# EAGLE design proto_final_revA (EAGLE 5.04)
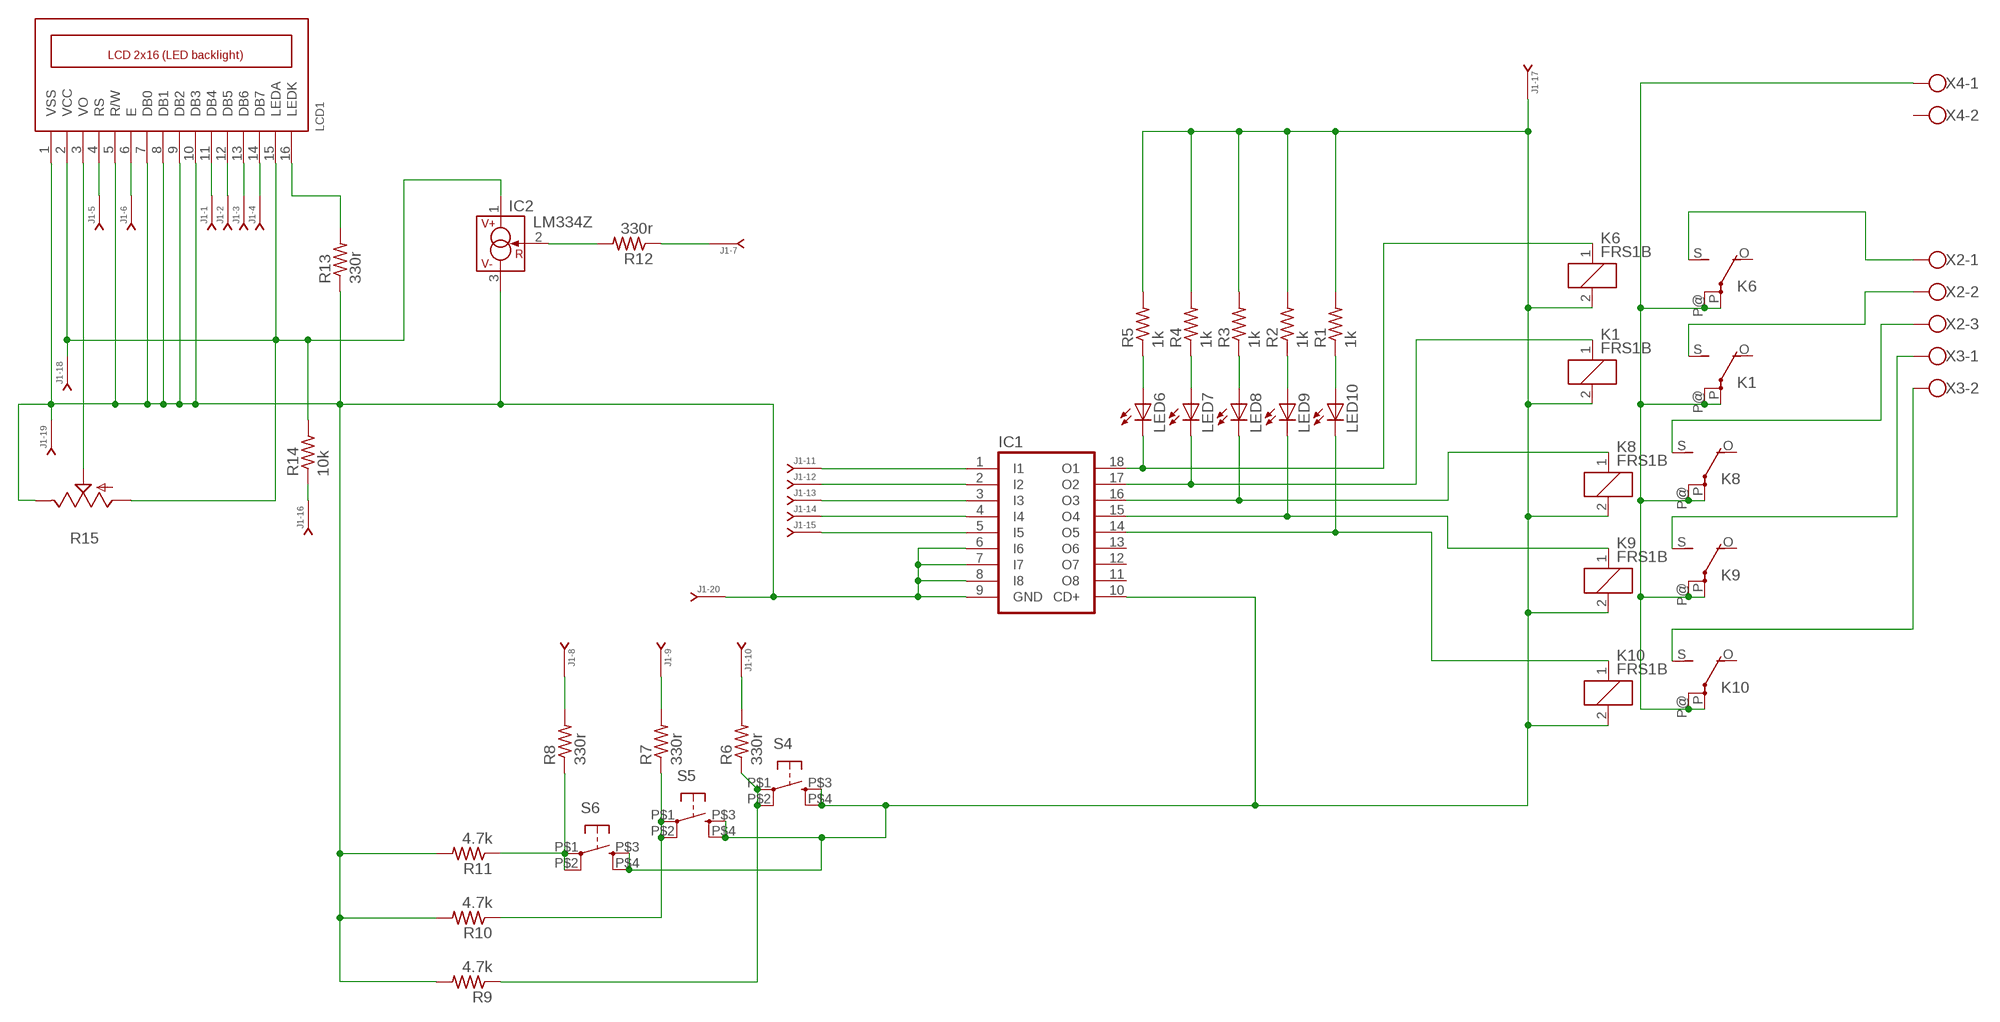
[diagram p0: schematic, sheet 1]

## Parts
IC1  ULN2803A  [DIL18]
IC2  LM334Z  [TO92]
J1  J-20-100-2X10  [HDR-100-2X10]
K1  FRS1B  [FRS1B]
K6  FRS1B  [FRS1B]
K8  FRS1B  [FRS1B]
K9  FRS1B  [FRS1B]
K10  FRS1B  [FRS1B]
LCD1  LCD_2X16_SIL  [HY-1602F]
LED6  LED5MM  [LED5MM]
LED7  LED5MM  [LED5MM]
LED8  LED5MM  [LED5MM]
LED9  LED5MM  [LED5MM]
LED10  LED5MM  [LED5MM]
R1  1k  R-US_0207/10  [0207/10]
R2  1k  R-US_0207/10  [0207/10]
R3  1k  R-US_0207/10  [0207/10]
R4  1k  R-US_0207/10  [0207/10]
R5  1k  R-US_0207/10  [0207/10]
R6  330r  R-US_0207/10  [0207/10]
R7  330r  R-US_0207/10  [0207/10]
R8  330r  R-US_0207/10  [0207/10]
R9  4.7k  R-US_0207/10  [0207/10]
R10  4.7k  R-US_0207/10  [0207/10]
R11  4.7k  R-US_0207/10  [0207/10]
R12  330r  R-US_0207/10  [0207/10]
R13  330r  R-US_0207/10  [0207/10]
R14  10k  R-US_0207/10  [0207/10]
R15  TRIM_US-CT6  [CT6]
S4  TAC_SWITCHKSA_SEALED  [KSA_SEALED_TAC_SWITCH]
S5  TAC_SWITCHKSA_SEALED  [KSA_SEALED_TAC_SWITCH]
S6  TAC_SWITCHKSA_SEALED  [KSA_SEALED_TAC_SWITCH]
X2  W237-103  [W237-103]
X3  W237-102  [W237-102]
X4  W237-102  [W237-102]

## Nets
GROUND: IC1.6(I6) IC1.7(I7) IC1.8(I8) IC1.9(GND) IC2.3(V-) J1.19 J1.20 LCD1.1(VSS) LCD1.5(R/W) LCD1.7(DB0) LCD1.8(DB1) LCD1.9(DB2) LCD1.10(DB3) R9.2 R10.2 R11.2 R13.1 R15.E
N$1: J1.6 LCD1.6(E)
N$2: J1.5 LCD1.4(RS)
N$3: J1.1 LCD1.11(DB4)
N$4: J1.2 LCD1.12(DB5)
N$5: J1.3 LCD1.13(DB6)
N$6: J1.4 LCD1.14(DB7)
N$7: IC2.2(R) R12.2
N$8: J1.7 R12.1
N$9: J1.8 R8.2
N$10: J1.9 R7.2
N$11: R8.1 R11.1 S6.P$1 S6.P$2
N$12: IC1.10(CD+) J1.17 K1.2 K6.2 K8.2 K9.2 K10.2 R1.2 R2.2 R3.2 R4.2 R5.2 S4.P$3 S4.P$4 S5.P$3 S5.P$4 S6.P$3 S6.P$4
N$13: LED6.A R5.1
N$14: K6.S(2:S) X2.1
N$15: K1.P(2:P) K1.P@(2:P) K6.P(2:P) K6.P@(2:P) K8.P(2:P) K8.P@(2:P) K9.P(2:P) K9.P@(2:P) K10.P(2:P) K10.P@(2:P) X4.1
N$16: J1.10 R6.2
N$17: IC1.1(I1) J1.11
N$18: IC1.2(I2) J1.12
N$19: IC1.3(I3) J1.13
N$20: IC1.4(I4) J1.14
N$21: IC1.5(I5) J1.15
N$22: LED7.A R4.1
N$23: LED8.A R3.1
N$24: LED9.A R2.1
N$25: LED10.A R1.1
N$26: IC1.18(O1) K6.1 LED6.K(C)
N$27: IC1.17(O2) K1.1 LED7.K(C)
N$28: IC2.1(V+) J1.18 LCD1.2(VCC) LCD1.15(LEDA) R14.2 R15.A
N$29: IC1.15(O4) K9.1 LED9.K(C)
N$30: IC1.14(O5) K10.1 LED10.K(C)
N$31: K1.S(2:S) X2.2
N$32: R7.1 R10.1 S5.P$1 S5.P$2
N$33: K8.S(2:S) X2.3
N$34: R6.1 R9.1 S4.P$1 S4.P$2
N$35: LCD1.3(VO) R15.S
N$36: IC1.16(O3) K8.1 LED8.K(C)
N$37: K9.S(2:S) X3.1
N$38: K10.S(2:S) X3.2
N$39: LCD1.16(LEDK) R13.2
N$40: J1.16 R14.1
Unconnected: IC1.11(O8) IC1.12(O7) IC1.13(O6) K1.O(2:O) K6.O(2:O) K8.O(2:O) K9.O(2:O) K10.O(2:O) X4.2

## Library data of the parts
IC1 = uln-udn:ULN2803A: DRIVER ARRAY
IC2 = linear:LM*34: 3-Terminal Adjustable Current Sources Source: www.national.com/pf/LM/LM334.html | LM134.pdf
J1 = con-headers-jp:J-20-: HEADER JACK PINS
K1 K6 K8-K10 = mgd:FRS1B: RELAY 1 x switch, same as V23101-D6-A201, Siemens
LCD1 = lcd_2x16_led_backlight:LCD_2X16_SIL
LED6-LED10 = SparkFun:LED: LEDs
R1-R14 = resistor:R-US_: RESISTOR, American symbol
R15 = pot:TRIM_US-: POTENTIOMETER
S4-S6 = SparkFun:TAC_SWITCH: Momentary Switch Button commonly used for reset or general input. Spark Fun Electronics SKU : COM-00097
X2 = con-wago-500:W237-103: WAGO SCREW CLAMP
X3 X4 = con-wago-500:W237-102: WAGO SCREW CLAMP

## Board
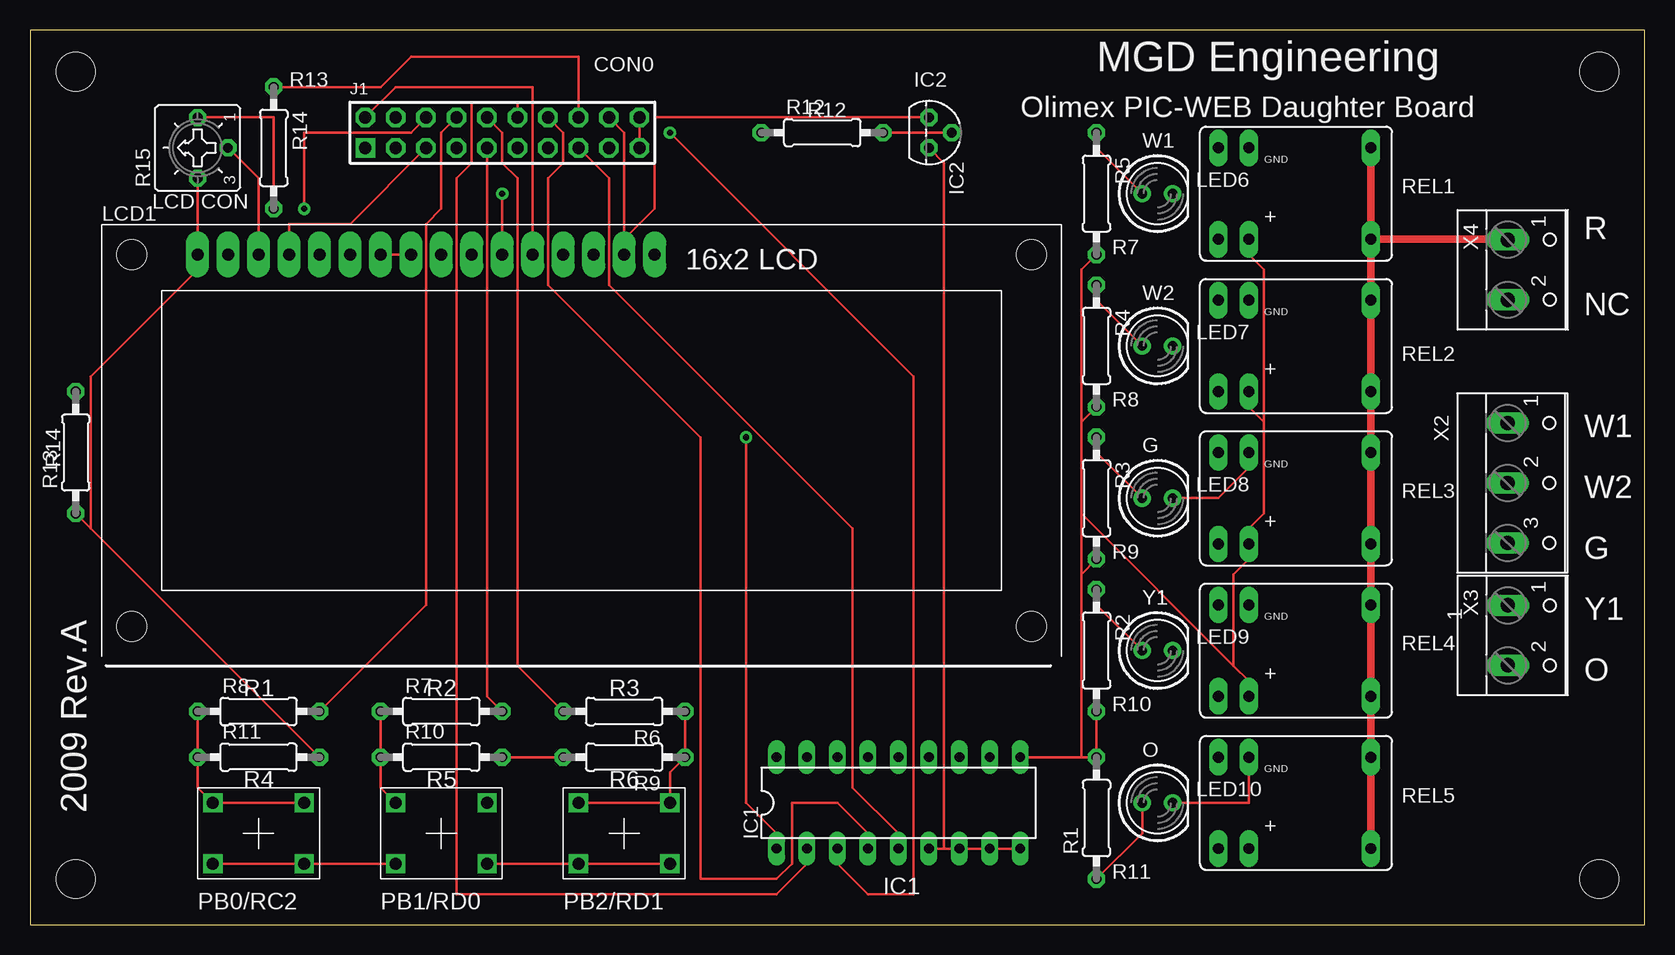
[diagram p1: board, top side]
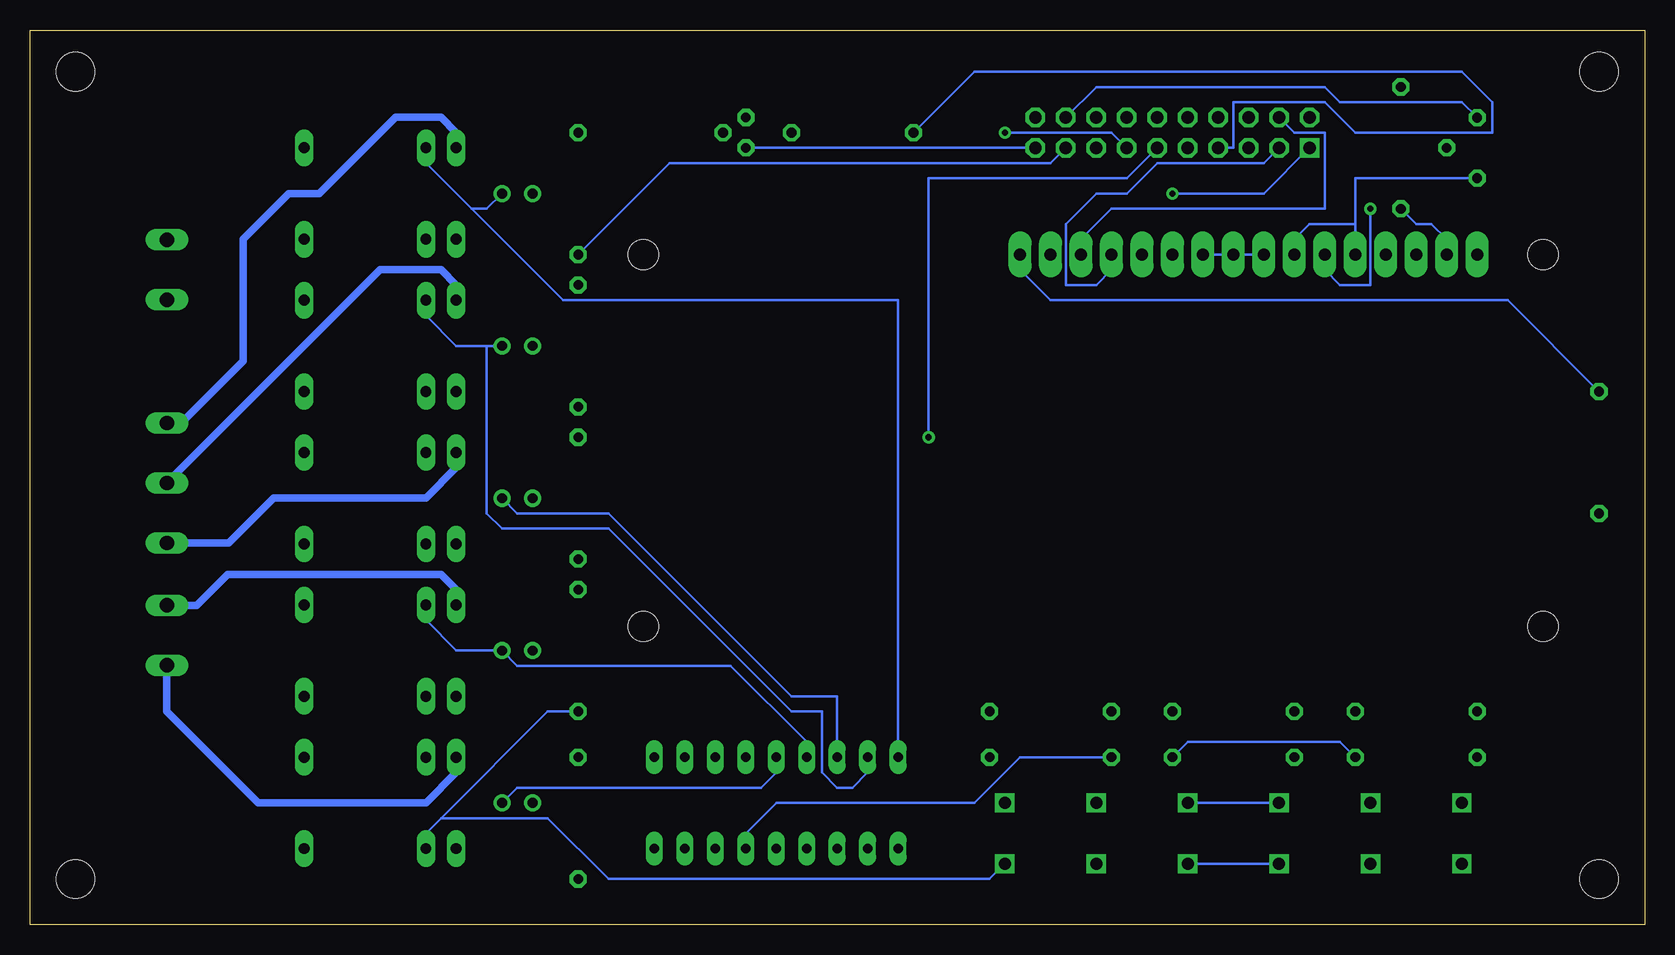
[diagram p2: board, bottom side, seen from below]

Size 134.6 x 74.6 mm. Coordinates in mm from the lower left corner, seen from the top.
Outline: 0,0 134.6,0 134.6,74.6 0,74.6 0,0
Copper layers (1*16): Top 0.035mm / dielectric 1.5mm / Bottom 0.035mm
Design rules "SparkFun": minimum track width 8mil, minimum drill 20mil, track to track 8mil, track to pad 8mil, pad to pad 8mil, via to via 8mil, smd to smd 8mil, copper to edge 10mil, drill to drill 8mil, minimum pad ring 12mil, minimum via ring 10mil, stop-mask expansion 4mil, vias tented up to drill 25mil, thermal gap 10mil
Holes 3.2 mm at 3.81,71.12 130.81,71.12 130.81,3.81 3.81,3.81

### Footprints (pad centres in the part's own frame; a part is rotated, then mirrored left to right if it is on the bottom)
DIL18 = drill 0.813 long: 1 -10.16,-3.81; 2 -7.62,-3.81; 3 -5.08,-3.81; 4 -2.54,-3.81; 5 0,-3.81; 6 2.54,-3.81; 7 5.08,-3.81; 8 7.62,-3.81; 9 10.16,-3.81; 10 10.16,3.81; 11 7.62,3.81; 12 5.08,3.81; 13 2.54,3.81; 14 0,3.81; 15 -2.54,3.81; 16 -5.08,3.81; 17 -7.62,3.81; 18 -10.16,3.81
TO92 = drill 0.813 octagon: 1 -1.27,0; 2 0,1.905; 3 1.27,0
HDR-100-2X10 = drill 1.016 square: 1 -11.43,-1.27 | drill 1.016 octagon: 2 -11.43,1.27; 3 -8.89,-1.27; 4 -8.89,1.27; 5 -6.35,-1.27; 6 -6.35,1.27; 7 -3.81,-1.27; 8 -3.81,1.27; 9 -1.27,-1.27; 10 -1.27,1.27; 11 1.27,-1.27; 12 1.27,1.27; 13 3.81,-1.27; 14 3.81,1.27; 15 6.35,-1.27; 16 6.35,1.27; 17 8.89,-1.27; 18 8.89,1.27; 19 11.43,-1.27; 20 11.43,1.27
FRS1B = drill 0.914 long: 1 0,3.81; 2 0,-3.81; O -2.54,-3.81; P 10.16,3.81; P@ 10.16,-3.81; S -2.54,3.81
HY-1602F = drill 1 pad 1.93 long: 1 2.54,0; 2 5.08,0; 3 7.62,0; 4 10.16,0; 5 12.7,0; 6 15.24,0; 7 17.78,0; 8 20.32,0; 9 22.86,0; 10 25.4,0; 11 27.94,0; 12 30.48,0; 13 33.02,0; 14 35.56,0; 15 38.1,0; 16 40.64,0 | hole 2.5: -2.96,0; 72.04,0; -2.96,-31; 72.04,-31
LED5MM = drill 0.813 round: A -1.27,0; K 1.27,0
0207/10 = drill 0.813 octagon: 1 -5.08,0; 2 5.08,0
CT6 = drill 0.813 octagon: A 2.515,0; E -2.515,0; S 0,-2.54
KSA_SEALED_TAC_SWITCH = drill 1 square: P$1 -3.81,2.54; P$2 3.81,2.54; P$3 -3.81,-2.54; P$4 3.81,-2.54
W237-103 = drill 1.194 long: 1 -5,-1.29; 2 0,-1.29; 3 5,-1.29
W237-102 = drill 1.194 long: 1 -2.5,-1.27; 2 2.5,-1.27

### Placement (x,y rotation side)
IC1  72.39,10.16 0 top
IC2  74.93,66.04 270 top
J1  39.37,66.04 0 top
K1  101.6,48.26 0 top
K6  101.6,60.96 0 top
K8  101.6,35.56 0 top
K9  101.6,22.86 0 top
K10  101.6,10.16 0 top
LCD1  11.43,55.88 0 top
LED6  93.98,60.96 0 top
LED7  93.98,48.26 0 top
LED8  93.98,35.56 0 top
LED9  93.98,22.86 0 top
LED10  93.98,10.16 0 top
R1  88.9,8.89 90 top
R2  88.9,22.86 270 top
R3  88.9,35.56 270 top
R4  88.9,48.26 270 top
R5  88.9,60.96 270 top
R6  49.53,17.78 180 top
R7  34.29,17.78 0 top
R8  19.05,17.78 0 top
R9  49.53,13.97 180 top
R10  34.29,13.97 0 top
R11  19.05,13.97 0 top
R12  66.04,66.04 0 top
R13  3.81,39.37 90 top
R14  20.32,64.77 270 top
R15  13.97,64.77 90 top
S4  49.53,7.62 0 top
S5  34.29,7.62 0 top
S6  19.05,7.62 0 top
X2  124.46,36.83 270 top
X3  124.46,24.13 270 top
X4  124.46,54.61 270 top

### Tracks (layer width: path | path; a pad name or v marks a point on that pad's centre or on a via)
GROUND
  Top 0.203: LCD1.7 LCD1.8 | R15.E LCD1.1 13.97,54.61 5.08,45.72 5.08,33.02 | J1.19 J1.20 | 76.2,6.35 IC1.7 IC1.8 IC1.9 | IC1.6 76.2,6.35 | R10.2 R9.2 | 5.08,33.02 R13.1 | R11.2 5.08,33.02 | IC2.3 76.2,63.5 76.2,6.35
  Bottom 0.203: LCD1.8 LCD1.9 LCD1.10 | 24.13,58.42 24.13,62.23 13.97,62.23 R15.E | 24.13,58.42 LCD1.5 | 24.13,58.42 27.94,58.42 29.21,57.15 LCD1.7 | IC2.3 J1.19 | R10.2 38.1,15.24 25.4,15.24 R11.2 | R9.2 52.07,13.97 55.88,10.16 72.39,10.16 74.93,7.62 IC1.6
N$1  (via drill 0.51)
  Top 0.203: J1.6 31.75,66.04 22.86,66.04 v22.86,59.69
  Bottom 0.203: v22.86,59.69 22.86,53.34 25.4,53.34 26.67,54.61 LCD1.6
N$2
  Top 0.203: J1.5 26.67,58.42 21.59,58.42 LCD1.4
N$3  (via drill 0.51)
  Top 0.203: v39.37,60.96 LCD1.11
  Bottom 0.203: J1.1 31.75,60.96 v39.37,60.96
N$4
  Top 0.203: J1.2 30.48,69.85 41.91,69.85 LCD1.12
N$5
  Bottom 0.203: J1.3 31.75,63.5 40.64,63.5 43.18,60.96 45.72,60.96 48.26,58.42 48.26,53.34 45.72,53.34 44.45,54.61 LCD1.13
N$6
  Bottom 0.203: J1.4 29.21,66.04 26.67,66.04 26.67,59.69 44.45,59.69 46.99,57.15 LCD1.14
N$7
  Top 0.203: R12.2 IC2.2
N$8
  Bottom 0.203: R12.1 55.88,71.12 15.24,71.12 12.7,68.58 12.7,66.04 24.13,66.04 26.67,68.58 34.29,68.58 34.29,64.77 J1.7
N$9
  Top 0.203: R8.2 33.02,26.67 33.02,58.42 34.29,59.69 34.29,66.04 J1.8
N$10
  Top 0.203: R7.2 38.1,19.05 J1.9
N$11
  Top 0.203: R8.1 R11.1 13.97,11.43 S6.P$1 S6.P$2
N$12
  Top 0.203: S6.P$3 S6.P$4 S5.P$3 | S5.P$4 S4.P$3 S4.P$4 | 87.63,13.97 R1.2 R2.2 | 87.63,13.97 IC1.10 | 87.63,29.21 R3.2 | 87.63,13.97 87.63,29.21 | 87.63,41.91 R4.2 | 87.63,29.21 87.63,34.29 | 87.63,34.29 87.63,41.91 | R5.2 87.63,54.61 87.63,41.91 | 87.63,34.29 100.33,21.59 | 100.33,21.59 101.6,20.32 K9.2 | 100.33,21.59 100.33,29.21 101.6,30.48 K8.2 101.6,33.02 102.87,34.29 102.87,41.91 | 102.87,41.91 101.6,43.18 K1.2 | 102.87,41.91 102.87,54.61 101.6,55.88 K6.2
  Bottom 0.203: S5.P$3 S5.P$4 | 100.33,8.89 91.44,17.78 R2.2 | 100.33,8.89 101.6,7.62 K10.2 | J1.17 49.53,63.5 81.28,63.5 R5.2 | S4.P$4 54.61,3.81 86.36,3.81 91.44,8.89 100.33,8.89
N$13
  Top 0.203: LED6.A 88.9,64.77 R5.1
N$14
  Bottom 0.61: K6.S 99.06,66.04 100.33,67.31 104.14,67.31 110.49,60.96 113.03,60.96 116.84,57.15 116.84,46.99 122,41.83 X2.1
N$15
  Top 0.203: 121.92,57.15 X4.1
  Top 0.61: K6.P@ 121.92,57.15 | K6.P@ K6.P | K6.P@ K1.P K1.P@ K8.P K8.P@ K9.P K9.P@ K10.P K10.P@
N$16
  Top 0.203: R6.2 40.64,21.59 40.64,62.23 39.37,63.5 39.37,66.04 J1.10
N$17  (via drill 0.51)
  Top 0.203: v59.69,40.64 59.69,10.16 62.23,7.62 IC1.1
  Bottom 0.203: v59.69,40.64 59.69,62.23 43.18,62.23 J1.11
N$18
  Top 0.203: J1.12 40.64,68.58 36.83,68.58 36.83,63.5 35.56,62.23 35.56,2.54 62.23,2.54 64.77,5.08 IC1.2
N$19  (via drill 0.51)
  Top 0.203: v53.34,66.04 73.66,45.72 73.66,2.54 69.85,2.54 67.31,5.08 IC1.3
  Bottom 0.203: v53.34,66.04 44.45,66.04 J1.13
N$20
  Top 0.203: J1.14 44.45,66.04 44.45,63.5 43.18,62.23 43.18,53.34 55.88,40.64 55.88,3.81 62.23,3.81 63.5,5.08 63.5,10.16 67.31,10.16 69.85,7.62 IC1.4
N$21
  Top 0.203: J1.15 48.26,62.23 48.26,53.34 68.58,33.02 68.58,11.43 72.39,7.62 IC1.5
N$22
  Top 0.203: LED7.A 88.9,52.07 R4.1
N$23
  Top 0.203: LED8.A 88.9,39.37 R3.1
N$24
  Top 0.203: LED9.A 88.9,26.67 R2.1
N$25
  Top 0.203: R1.1 92.71,7.62 LED10.A
N$26
  Bottom 0.203: 97.79,59.69 101.6,63.5 K6.1 | 97.79,59.69 90.17,52.07 62.23,52.07 IC1.18 | LED6.K 96.52,59.69 97.79,59.69
N$27
  Bottom 0.203: 96.52,48.26 96.52,34.29 95.25,33.02 86.36,33.02 71.12,17.78 68.58,17.78 68.58,12.7 67.31,11.43 66.04,11.43 64.77,12.7 IC1.17 | 96.52,48.26 LED7.K | 96.52,48.26 99.06,48.26 101.6,50.8 K1.1
N$28
  Top 0.203: R14.2 20.32,67.31 13.97,67.31 R15.A | IC2.1 52.07,67.31 52.07,59.69 49.53,57.15 | J1.18 49.53,66.04 49.53,57.15 | 49.53,57.15 LCD1.15
  Bottom 0.203: R14.2 19.05,58.42 17.78,58.42 16.51,57.15 LCD1.2 | J1.18 45.72,69.85 26.67,69.85 25.4,68.58 15.24,68.58 13.97,67.31 R15.A
N$29
  Bottom 0.203: IC1.15 69.85,15.24 76.2,21.59 93.98,21.59 LED9.K 99.06,22.86 101.6,25.4 K9.1
N$30
  Top 0.203: LED10.K 101.6,10.16 K10.1
  Bottom 0.203: LED10.K 93.98,11.43 73.66,11.43 72.39,12.7 IC1.14
N$31
  Bottom 0.61: K1.S 99.06,53.34 100.33,54.61 105.41,54.61 123.17,36.85 X2.2
N$32
  Top 0.203: R7.1 R10.1 29.21,11.43 S5.P$1
  Bottom 0.203: S5.P$1 S5.P$2
N$33
  Bottom 0.61: X2.3 118.03,31.83 114.3,35.56 101.6,35.56 99.06,38.1 K8.S
N$34
  Top 0.203: R6.1 R9.1 53.34,12.7 S4.P$2 S4.P$1
N$35
  Top 0.203: R15.S 19.05,62.23 LCD1.3
N$36
  Top 0.203: LED8.K 99.06,35.56 101.6,38.1 K8.1
  Bottom 0.203: LED8.K 93.98,34.29 86.36,34.29 71.12,19.05 67.31,19.05 IC1.16
N$37
  Bottom 0.61: X3.1 120.69,26.63 118.11,29.21 100.33,29.21 99.06,27.94 K9.S
N$38
  Bottom 0.61: X3.2 123.19,17.78 115.57,10.16 101.6,10.16 99.06,12.7 K10.S
N$39
  Bottom 0.203: R13.2 11.43,52.07 49.53,52.07 52.07,54.61 LCD1.16
N$40
  Top 0.203: R14.1 29.21,69.85 31.75,72.39 45.72,72.39 J1.16

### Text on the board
tPlace: CON0 | MGD Engineering | R13 | IC2 | R12 | Olimex PIC-WEB Daughter Board | W1 | REL1 | LCD CON | R | R7 | 16x2 LCD | W2 | NC | REL2 | R8 | 1 | W1 | G | R14 | 2 | REL3 | W2 | 3 | R9 | G | Y1 | 2009 Rev.A | 1 | Y1 | REL4 | O | R1 | R2 | R3 | R10 | O | R4 | R5 | R6 | REL5 | R11 | IC1 | PB0/RC2 | PB1/RD0 | PB2/RD1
